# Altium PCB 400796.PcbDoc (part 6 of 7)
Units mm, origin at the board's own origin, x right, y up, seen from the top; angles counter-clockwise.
Board outline 53 x 53 mm, 6 copper layers (Top Layer, Mid Layer 1, Mid Layer 2, Mid Layer 3, Mid Layer 4, Bottom Layer), stack 1.494 mm thick; 319 components, 236 nets, 1249 pads, 2569 vias.
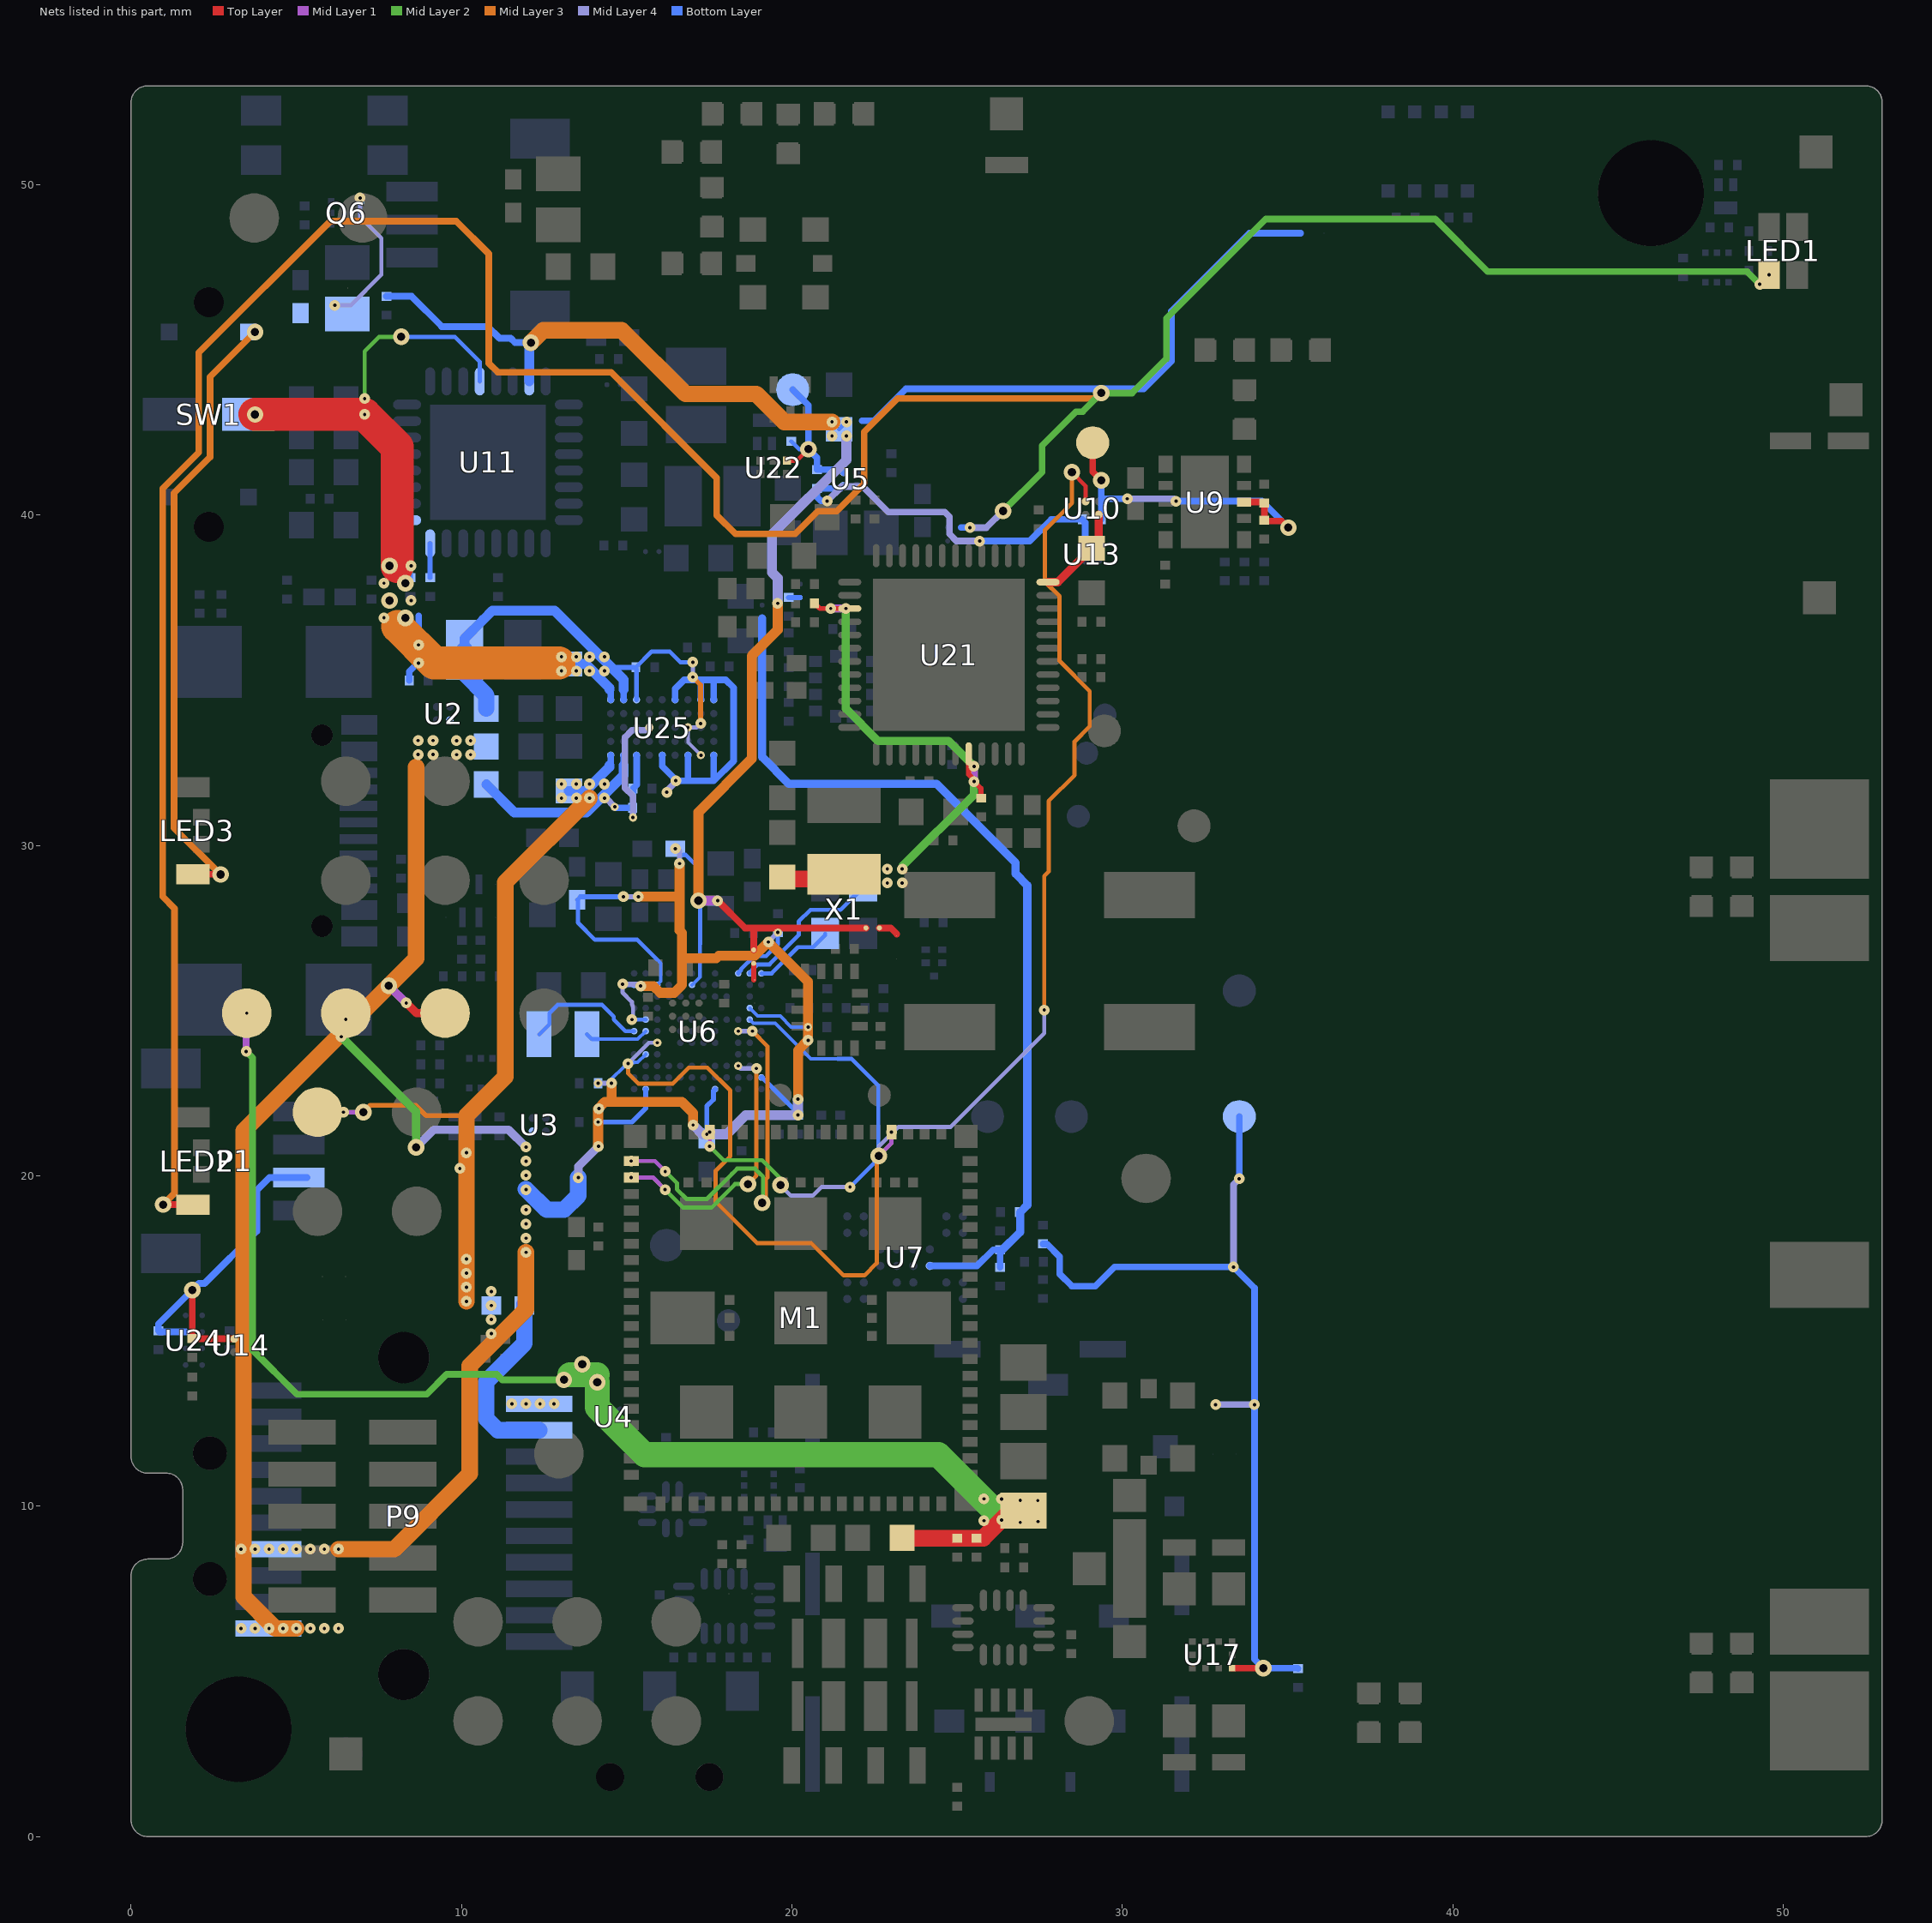
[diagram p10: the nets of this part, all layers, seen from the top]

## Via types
v1: diameter 0.325, hole 0.1, Mid Layer 4 to Bottom Layer, tented both sides, 675 vias
v2: diameter 0.325, hole 0.1, Top Layer to Mid Layer 1, tented both sides, 569 vias
v3: diameter 0.325, hole 0.1, Mid Layer 3 to Mid Layer 4, tented both sides, 384 vias
v4: diameter 0.5, hole 0.25, Mid Layer 1 to Mid Layer 4, tented both sides, 312 vias
v5: diameter 0.325, hole 0.1, Mid Layer 1 to Mid Layer 2, tented both sides, 265 vias
v6: diameter 0.5, hole 0.25, Top Layer to Bottom Layer, tented both sides, 175 vias
v7: diameter 0.25, hole 0.1, Mid Layer 4 to Bottom Layer, tented both sides, 105 vias
v8: diameter 0.325, hole 0.1, Top Layer to Mid Layer 1, tented top, 67 vias
v9: diameter 0.25, hole 0.1, Top Layer to Mid Layer 1, tented both sides, 17 vias

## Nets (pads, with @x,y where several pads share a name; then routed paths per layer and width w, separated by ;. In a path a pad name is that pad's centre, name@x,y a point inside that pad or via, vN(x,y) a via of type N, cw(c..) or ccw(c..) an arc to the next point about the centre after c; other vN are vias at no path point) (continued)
VCOM0.TXD: M1.56 U6.E2 | length 13.7
  Mid Layer 1 w0.125: v5(17.513,20.895) v2(17.513,21.325)
  Mid Layer 2 w0.125: v5(17.513,20.895) 17.932,20.477 19.099,20.477 19.653,19.923 v4(19.653,19.72)
  Mid Layer 4 w0.125: v4(19.653,19.72) 19.97,19.403 20.631,19.403 20.891,19.663 v1(21.758,19.663)
  Bottom Layer w0.105: U6.E2@18.725,24.73 18.832,24.623 19.497,24.623 20.573,23.546 21.387,23.546
  Bottom Layer w0.125: 21.387,23.546 21.802,23.546 22.613,22.735 22.613,20.518 v1(21.758,19.663)
VCOM1.RXD: M1.62 U6.J3 | length 8.4
  Mid Layer 1 w0.125: v2(15.138,19.95) 15.798,19.95 v5(16.163,19.585)
  Mid Layer 2 w0.125: v5(16.163,19.585) 16.711,19.038 17.562,19.038 18.277,19.753 v4(18.672,19.753)
  Mid Layer 3 w0.125: v4(18.672,19.753) 18.927,20.007 v3(18.927,23.254)
  Mid Layer 4 w0.15: v7(18.375,23.33) 18.451,23.254 v3(18.927,23.254)
VCOM1.TXD: M1.61 U6.F3 | length 11.7
  Mid Layer 1 w0.125: v2(15.138,20.45) 15.853,20.45 v5(16.167,20.136)
  Mid Layer 2 w0.125: v5(16.167,20.136) 16.519,19.783 16.519,19.594 16.812,19.301 17.424,19.301 18.185,20.062 18.341,20.218 18.882,20.218 19.039,20.062 19.123,19.978 19.123,19.212 v4(19.096,19.185)
  Mid Layer 3 w0.127: v3(18.806,24.38) 19.259,23.927 19.259,19.95 19.214,19.906 19.214,19.303 v4(19.096,19.185)
  Mid Layer 4 w0.15: v7(18.375,24.38) v3(18.806,24.38)
VDD_ACC: R26.1 ST7.2 | length 0.4
  Bottom Layer w0.152: R26.1@19.9,37.51 ST7.2@20.253,37.51
VDD_BMI270: SB4.1 ST1.2 | length 0.6
  Top Layer w0.203: ST1.2@22.648,27.506 22.99,27.506 23.173,27.323
VDD_BMM350: SB10.1 ST4.2 | length 0.5
  Top Layer w0.152: 18.841,25.928 ST4.2@18.841,26.434
VDD_BUCK: C60.2 C65.2 C70.2 L6.2 U21.15 U21.32 | length 17
  Top Layer w0.152: C70.2@20.68,37.338 20.68,37.323 20.739,37.264 20.754,37.264 20.843,37.175 v2(21.175,37.175) U21.15@21.75,37.175 ; U21.32@25.35,32.775 25.35,32.153 25.513,31.99 v2(25.513,31.94) 25.725,31.728 C60.2@25.725,31.435
  Top Layer w0.508: C65.2@19.83,28.993 L6.2@20.942,28.993 ; L6.2@21.075,29.127 L6.2@20.942,28.993 ; L6.2@21.442,28.993 L6.2@20.942,28.993
  Mid Layer 1 w0.25: v2(21.175,37.175) v5(21.632,37.175) ; v2(25.513,31.94) v5(25.513,32.397)
  Mid Layer 2 w0.25: v5(21.632,37.175) 21.632,34.146 22.613,33.165 24.745,33.165 v5(25.513,32.397) 25.513,31.54 23.338,29.365 v5(23.338,29.292)
  other v2: 22.888,28.867 22.888,29.292
  other v5: 23.338,28.867
VDD_ENV: SB5.1 ST5.2 | length 16.5
  Bottom Layer w0.2: ST5.2@22.128,42.859 22.484,42.859 23.45,43.825 30.65,43.825 31.487,44.662 31.487,46.176 33.849,48.538 SB5.1@35.4,48.538
VDD_EXP_BRD: C76.2 P1.2 R5.1 U14.A1 U24.B2 | length 10.8
  Top Layer w0.203: v6(1.854,16.544) R5.1@1.854,15.072 3.109,15.072 U14.A1@3.11,15.073
  Bottom Layer w0.203: U24.B2@1.65,15.275 0.86,15.275 C76.2@0.825,15.31 0.825,15.516 v6@1.815,16.506 ; v6(1.854,16.544) 2.051,16.742 2.223,16.742 3.802,18.321 3.802,19.562 4.19,19.95 P1.2@5.325,19.95
VDD_LED: LED1.4 LED2.4 ST2.2 | length 96.1
  Top Layer w0.2: v6(0.968,19.129) LED2.4@1.873,19.129
  Mid Layer 1 w0.15: v5(49.292,46.992) v2(49.575,47.275)
  Mid Layer 2 w0.2: v4(26.393,40.129) 27.571,41.307 27.571,42.108 28.595,43.132 28.797,43.132 v4(29.365,43.7) 30.301,43.7 31.339,44.738 31.339,45.958 34.349,48.968 39.465,48.968 41.06,47.373 48.911,47.373 v5(49.292,46.992)
  Mid Layer 3 w0.2: v6(0.968,19.129) 1.313,19.475 1.313,28.094 0.954,28.453 0.954,40.812 2.046,41.904 2.046,44.922 6.024,48.9 9.841,48.9 10.825,47.916 10.825,44.6 11.1,44.325 14.528,44.325 17.725,41.128 17.725,40 18.292,39.433 20.094,39.433 20.786,40.125 21.352,40.125 22.185,40.958 22.185,42.519 23.203,43.537 29.203,43.537 v4(29.365,43.7)
  Mid Layer 4 w0.2: v1(25.39,39.625) 25.889,39.625 v4(26.393,40.129)
  Bottom Layer w0.2: ST2.2@25.121,39.628 25.387,39.628 v1(25.39,39.625)
VDD_MEM: C37.2 R43.2 R50.2 ST9.2 U7.C3 | length 28.3
  Bottom Layer w0.2: U7.C3@24.175,17.275 25.6,17.275 26.09,17.765 C37.2@26.3,17.765 R50.2@26.3,17.235
  Bottom Layer w0.25: ST9.2@19.1,36.875 ST9.2@19.1,36.872 19.1,32.675 19.907,31.868 24.381,31.868 26.77,29.479 26.77,29.145 27.125,28.79 27.125,19.115 26.91,18.9 26.91,18.297 C37.2@26.326,17.713
VDD_nRF53: C12.1 C13.1 C15.1 C16.1 C19.1 C20.1 C21.1 C22.2 P9.4 TP2.1 U3.A1 U6.A3 U6.B7 U6.B10 U6.B12 U6.D2 U6.E11 U6.H11 U6.K1 U6.L5 U6.L11 | length 75
  Top Layer w0.15: v2(6.498,24.734) 6.5,24.735 TP2.1@6.5,24.927
  Mid Layer 1 w0.15: v5(6.358,24.212) 6.498,24.352 v2(6.498,24.734)
  Mid Layer 2 w0.254: v5(6.358,24.212) 8.624,21.945 v4(8.624,20.863)
  Mid Layer 3 w0.3: v3@14.135,20.905 14.135,22.035 14.34,22.24 16.672,22.24 17.008,21.904 v3(17.008,21.537) ; 14.54,22.25 v3(14.54,22.805) ; v3(15.35,28.45) 16.6,28.45 ; v3(15.42,25.746) 15.81,25.746 16.014,25.542 16.436,25.542 16.676,25.783 16.676,26.583 ; v3(16.6,29.455) 16.6,28.45 ; v3(20.184,22.321) 20.184,23.799 v3(20.49,24.105) 20.49,25.879 v3(19.287,27.082) 18.874,26.67 17.792,26.67 17.705,26.583 16.676,26.583 ; 16.6,28.45 16.6,27.433 16.676,27.356 16.676,26.583
  Mid Layer 3 w0.5: v3(6.275,8.7) 7.969,8.7 10.25,10.981 10.25,14.25 11.95,15.95 v3(11.95,17.685)
  Mid Layer 4 w0.125: v1(14.875,25.805) 14.875,25.55 15.156,25.268 15.156,25.187 15.17,25.174 15.17,25.166 15.178,25.158 15.178,25.126 15.191,25.113 15.191,24.763 v1(15.159,24.73)
  Mid Layer 4 w0.15: v7(14.135,21.63) v3@14.135,22.03 ; v7(14.135,22.805) v3@14.535,22.805 ; v1(14.875,25.805) 15.361,25.805 v3(15.42,25.746) ; v1(14.9,28.45) v3(15.35,28.45) ; v3(16.6,29.455) v1@16.6,29.855 ; v3@19.292,27.087 v7(19.575,27.37) ; v3(20.49,24.105) v7(20.49,24.505)
  Mid Layer 4 w0.254: v4(8.624,20.863) 9.157,21.395 11.43,21.395 v1(11.95,20.875) ; v1(13.534,19.949) 13.534,20.285 v3(14.145,20.895)
  Mid Layer 4 w0.3: v3(17.008,21.537) 17.017,21.537 17.298,21.257 v1(17.425,21.257)
  Mid Layer 4 w0.305: v1(17.425,21.257) 18.016,21.257 18.599,21.84 v1(20.184,21.84) v3(20.184,22.321)
  Bottom Layer w0.105: C20.1@14.148,22.805 14.41,22.805 15.037,23.433 15.22,23.433 15.225,23.437 15.332,23.437 U6.H11@15.575,23.68 ; 15.92,26.55 16.032,26.438 16.032,25.887 U6.B10@15.925,25.78 ; U6.B7@16.975,25.78 17.217,26.023 17.217,27.05 ; U6.D2@18.725,25.08 18.967,24.838 19.65,24.838 19.98,24.507 C12.1@20.471,24.507
  Bottom Layer w0.125: C22.2@13.5,28.355 C22.2@13.595,28.45 ; C22.2@13.525,28.355 13.525,27.665 14.039,27.151 15.319,27.151 15.92,26.55 ; v7(14.135,22.805) C20.1@14.148,22.805 ; v1(15.159,24.73) U6.E11@15.575,24.73 ; v1(16.475,29.905) 16.662,29.718 16.787,29.718 17.225,29.28 17.225,27.025 ; U6.A3@18.375,26.13 18.375,26.142 18.452,26.22 18.452,26.246 18.858,26.653 19.218,26.653 19.575,27.009 C21.1@19.575,27.27
  Bottom Layer w0.15: C22.2@13.595,28.45 v1(14.9,28.45) ; v7(14.135,21.63) 15.157,21.63 15.575,22.047 U6.L11@15.575,22.63 ; v1(14.875,25.805) 14.9,25.78 U6.B12@15.225,25.78 ; v1(17.425,21.257) 17.425,22.114 17.623,22.312 17.623,22.579 U6.L5@17.675,22.63 ; U6.K1@19.075,22.98 19.078,22.976 19.103,22.976 C13.1@20.184,21.896
  Bottom Layer w0.5: v1@11.95,19.6 12.575,18.975 13.104,18.975 13.534,19.405 v1(13.534,19.949)
  other v1: 3.325,8.7 3.75,8.7 4.175,8.7 4.6,8.7 11.95,19.585 11.95,20.015 11.95,20.445
  other v3: 5,8.7 5.425,8.7 5.85,8.7 11.95,18.115 11.95,18.545 11.95,18.975 14.16,22.035
VDD_nRF91: C1.1 C2.1 C3.1 FB1.1 P9.11 TP3.1 U4.A1 | length 39.5
  Top Layer w0.508: FB1.1@23.332,9.03 C2.1@25.587,9.03 ; C2.1@25.583,9.033 25.791,9.033 26.623,9.865 C3.1@27.006,9.865
  Mid Layer 1 w0.203: v5(3.481,23.767) 3.481,24.909 v2(3.5,24.927)
  Mid Layer 2 w0.203: v5(3.481,23.767) 3.675,23.573 3.675,14.731 5.016,13.391 8.95,13.391 9.551,13.991 11.069,13.991 11.234,13.826 v4(13.099,13.826)
  Mid Layer 2 w0.762: v4@13.283,13.979 v4@14.109,13.979 ; v4(14.109,13.75) 14.109,12.993 15.543,11.558 24.436,11.558 25.792,10.203 26.129,9.865
  other v1: 11.525,13.1 11.95,13.1 12.375,13.1 12.8,13.1
  other v2: 26.911,9.511 27.446,9.534 26.911,10.174 27.442,10.171
  other v4: 13.655,14.301
  other v5: 25.813,9.56 26.348,9.583 25.813,10.223 26.344,10.22
VDD_nRF91_RES: P9.12 R24.1 U4.A2 | length 5.7
  Bottom Layer w0.5: R24.1@11.9,16.113 11.9,14.925 10.75,13.775 10.75,12.65 11.1,12.3 P9.12@12.35,12.3
VDD_RF_FE_3V3: C32.2 C33.2 R56.1 TP8.1 U9.3 U13.A1 | length 10.9
  Top Layer w0.2: TP8.1@29.105,42.194 29.105,41.314 v6(29.36,41.059) ; U9.3@33.688,40.4 34.133,40.4 ; C32.2@34.3,40.233 34.3,39.825 34.825,39.825 v6(35.025,39.625)
  Mid Layer 4 w0.2: v1(30.15,40.5) 31.55,40.5 v1(31.625,40.425)
  Bottom Layer w0.2: U13.A1@29.275,39.028 R56.1@29.275,39.793 ; R56.1@29.36,39.878 29.36,40.5 ; v6(29.36,41.059) 29.36,40.5 ; v1(30.15,40.5) 29.36,40.5 ; v1(31.625,40.425) 34.225,40.425 v6(35.025,39.625)
VDD_RF_FE_3V3_SP: R25.2 R56.2 ST3.2 U5.A2 U13.A2 | length 12.1
  Mid Layer 4 w0.2: v1(21.069,40.431) 21.506,40.868 22.146,40.868 22.918,40.096 24.624,40.096 24.766,39.954 24.766,39.433 24.979,39.219 v1(25.683,39.219)
  Bottom Layer w0.2: v1(21.069,40.431) 20.879,40.431 20.761,40.549 R25.2@20.761,40.814 21.476,40.814 U5.A2@21.561,40.899 ; ST3.2@25.121,39.219 v1(25.683,39.219) 27.194,39.219 27.853,39.878 R56.2@28.79,39.878 ; R56.2@28.783,39.878 R56.2@28.786,39.875 ; R56.2@28.79,39.863 28.875,39.778 U13.A2@28.875,39.028
VDD_RF_FE_SR: R25.1 R62.1 TP11.1 U5.A1 U22.4 | length 5
  Top Layer w0.125: U22.4@19.85,41.65 20.15,41.65 v6(20.5,42)
  Bottom Layer w0.125: R62.1@19.975,42.24 20.215,42 v6(20.5,42)
  Bottom Layer w0.2: TP11.1@20.025,43.8 20.5,43.325 v6(20.5,42) 20.761,41.739 R25.1@20.761,41.384 21.476,41.384 U5.A1@21.561,41.299
VDD_SENS: C90.2 R30.2 ST1.1 ST4.1 ST5.1 U11.31 | length 39.5
  Top Layer w0.203: v2(17.753,28.332) 18.579,27.506 18.846,27.506 ; ST4.1@18.841,26.84 18.841,27.501 18.846,27.506 ; ST1.1@22.242,27.506 18.846,27.506
  Mid Layer 1 w0.305: v4(17.172,28.332) v2(17.753,28.332)
  Mid Layer 3 w0.305: v4(17.172,28.332) 17.172,31.016 18.787,32.631 18.787,35.744 19.569,36.526 v3(19.569,37.332)
  Mid Layer 3 w0.5: v6(12.1,45.225) 12.475,45.6 14.85,45.6 16.779,43.671 18.923,43.671 19.769,42.825 v3(21.213,42.825)
  Mid Layer 4 w0.125: v1(21.213,42.4) v3(21.213,42.825)
  Mid Layer 4 w0.305: v3(19.569,37.332) 19.569,38.098 19.398,38.269 19.398,39.421 21.65,41.674 v1(21.65,42.4)
  Bottom Layer w0.125: C90.2@21.425,42.6 21.684,42.859 ST5.1@21.722,42.859
  Bottom Layer w0.203: R30.2@7.726,46.628 8.485,46.628 9.401,45.712 10.795,45.712 11.149,45.358 11.487,45.358 11.62,45.225 v6@12.05,45.225
  Bottom Layer w0.3: U11.31@12.05,44.05 12.05,45.225 v6(12.1,45.225)
  other v3: 21.65,42.825
VDDIO_CTRL: M1.45 U6.G10 U10.B2 | length 45
  Top Layer w0.125: v6(28.475,41.3) 28.888,40.887 U10.B2@28.888,40.415
  Mid Layer 1 w0.125: v4(22.629,20.604) 23.013,20.988 v2(23.013,21.325)
  Mid Layer 3 w0.125: v3(15.039,23.4) 15.039,23.104 15.347,22.795 16.394,22.795 16.875,23.276 17.441,23.276 18.134,22.583 18.134,20.598 17.693,20.157 17.693,19.222 18.953,17.962 20.586,17.962 21.562,16.987 22.196,16.987 22.567,17.357 22.567,20.542 v4(22.629,20.604) ; v3(27.637,25.023) 27.637,29.079 27.771,29.213 27.771,31.349 28.555,32.134 28.555,33.147 29.014,33.606 29.014,34.671 28.097,35.588 28.097,37.548 27.657,37.988 27.657,39.555 28.475,40.373 v6(28.475,41.3)
  Mid Layer 4 w0.125: v3(15.039,23.4) 15.669,24.03 v7(15.925,24.03) ; v4(22.629,20.604) 22.629,20.887 23.225,21.483 24.803,21.483 27.637,24.317 v3(27.637,25.023)
VDDIO_nRF70: C30.2 U10.A1 U21.48 | length 2.8
  Top Layer w0.254: U21.48@27.75,37.975 28.05,37.975 C30.2@29.075,39 C30.2@29.263,39.188 ; C30.2@29.288,39.188 U10.A1@29.288,40.015
VIO: C38.2 R29.2 SB1.1 TP21.1 U17.4 | length 27.1
  Top Layer w0.2: U17.4@33.318,5.1 v6(34.268,5.1)
  Mid Layer 4 w0.2: v1(32.825,13.075) v1(34,13.075) ; v1@33.364,17.266 33.364,19.738 v1(33.537,19.911)
  Bottom Layer w0.2: R29.2@27.6,17.94 27.71,17.94 28.102,17.549 28.102,17.031 28.476,16.656 29.183,16.656 29.768,17.241 v1(33.364,17.241) 34,16.605 v1(34,13.075) 34,5.368 v6(34.268,5.1) 35.305,5.1 C38.2@35.32,5.085 ; v1(33.537,19.911) 33.54,19.914 TP21.1@33.54,21.795
VOUT_BUCK0: C78.2 C82.1 L9.2 U25.B1 U25.C3 U25.G5 U25.H5 | length 16.1
  Mid Layer 3 w0.15: v3(17,35.1) 17.237,34.863 v3(17.237,33.695)
  Mid Layer 4 w0.105: v7(16.855,33.575) 16.855,33.125 v7(17.245,32.735)
  Mid Layer 4 w0.125: v7(16.855,33.575) 17.116,33.575 v3(17.237,33.695) ; v3(17,35.1) v1(17,35.55)
  Bottom Layer w0.125: C82.1@15.225,35.39 15.271,35.39 15.756,35.875 16.3,35.875 16.625,35.55 v1(17,35.55)
  Bottom Layer w0.15: 14.56,35.39 C82.1@15.225,35.39 ; U25.G5@15.295,34.415 C82.1@15.295,35.331
  Bottom Layer w0.2: U25.H5@14.905,34.415 14.905,34.72
  Bottom Layer w0.3: L9.2@10.09,35.925 10.09,36.27 10.655,36.835 10.93,37.11 12.815,37.11 14.905,35.02 14.905,34.72
  Bottom Layer w0.5: L9.2@10.09,35.925 10.09,35.21 10.75,34.55 C78.2@10.75,34.15
VOUT_BUCK3: C81.2 L10.2 P9.1 TP14.1 U2.A2 U25.H1 | length 36.9
  Top Layer w0.254: v2(8.328,25.233) 8.332,25.233 8.638,24.927 TP14.1@9.5,24.927
  Mid Layer 1 w0.254: v4(7.799,25.756) 7.805,25.756 v2(8.328,25.233)
  Mid Layer 3 w0.5: v3(5,6.3) 4.362,6.3 3.4,7.262 3.4,21.356 v4(7.799,25.756) 8.625,26.581 8.625,32.375
  Bottom Layer w0.2: 14.905,32.43 U25.H1@14.905,32.735
  Bottom Layer w0.3: L10.2@10.75,31.85 11.6,31 13.775,31 14.905,32.13 14.905,32.43
  other v1: 3.325,6.3 3.75,6.3 4.175,6.3 4.6,6.3 9.85,32.75 10.275,32.75 9.85,33.175 10.275,33.175
  other v3: 5.425,6.3 5.85,6.3 6.275,6.3 8.688,32.755 9.138,32.755 8.688,33.18 9.138,33.18
VSET1: R7.1 U11.17 | length 1.9
  Bottom Layer w0.15: U11.17@8.1,39.781 8.169,39.85 U11.17@8.35,39.85 ; R7.1@8.45,38.11 U11.17@8.45,39.781
VSET2: R8.1 U11.16 | length 1
  Bottom Layer w0.15: R8.1@9.05,38.11 U11.16@9.05,39.15
VSYS: C98.2 FB5.2 LED3.4 Q6.4 SW1.6 | length 23.2
  Top Layer w0.2: LED3.4@1.873,29.129 2.699,29.129 v6(2.705,29.123)
  Mid Layer 3 w0.2: v6(2.705,29.123) 1.299,30.53 1.299,40.669 2.388,41.758 2.388,44.188 v6(3.75,45.55)
  Mid Layer 4 w0.125: v1(6.165,46.357) 6.647,46.357 7.573,47.283 7.573,48.39 6.929,49.034 v1(6.929,49.605)
VSYS_SW: C77.2 C80.2 C83.1 C84.1 R3.2 R24.2 SW1.5 TP17.1 U11.28 U25.A1 U25.A5 U25.B5 U25.C1 U25.D5 U25.E1 U25.F3 U25.G1 U25.J1 U25.J5 | length 65.6
  Top Layer w0.152: TP17.1@5.642,21.927 v2(6.428,21.927)
  Top Layer w1: v6(3.75,43.05) v2(7.067,43.05) 8.05,42.067 8.05,38.45
  Mid Layer 1 w0.125: v2(7.067,43.05) v5(7.067,43.533)
  Mid Layer 1 w0.152: v2(6.428,21.927) v4(7.026,21.927)
  Mid Layer 2 w0.125: v5(7.067,43.533) 7.067,44.962 7.507,45.402 v6(8.175,45.402)
  Mid Layer 3 w0.152: v4@6.976,21.927 v4@7.001,21.953 ; v4(7.026,21.927) 7.234,22.135 8.615,22.135 8.925,21.825 10.15,21.825
  Mid Layer 3 w0.3: 10.148,19.9 10.15,19.898
  Mid Layer 3 w0.5: v3(10.15,16.2) v3(10.15,16.63) v3(10.15,17.055) v3(10.15,17.48) 10.15,19.898 10.15,21.825 11.325,23 11.325,28.887 v3(13.875,31.437)
  Mid Layer 3 w1: 8.063,36.637 9.175,35.525 12.95,35.525
  Mid Layer 4 w0.2: v3(8.7,35.525) v1(8.7,36.075) ; v3(14.325,31.438) 14.369,31.438 v7(14.637,31.17) ; v7(15.19,30.851) 15.19,31.501 14.945,31.746 14.945,33.275 15.16,33.49 15.6,33.49 v7(15.685,33.575) ; v3@16.214,31.663 v1@16.513,31.962
  Mid Layer 4 w0.3: v1(9.95,20.225) 10.15,20.425 v3(10.15,20.7)
  Bottom Layer w0.125: v6(8.175,45.402) 9.798,45.402 10.55,44.65 U11.28@10.55,44.05
  Bottom Layer w0.2: R3.2@8.415,35 8.415,35.265 8.7,35.55 v1(8.7,36.075) 8.7,36.95 ; 14.515,32.43 U25.J1@14.515,32.735 ; U25.J5@14.515,34.415 14.515,34.72 ; v7(14.637,31.17) 14.662,31.145 C83.1@15.177,31.145 C83.1@15.19,31.132 ; v7(15.19,30.851) C83.1@15.19,31.132 ; U25.G1@15.295,32.735 15.299,32.731 15.299,32.717 15.305,32.711 15.305,31.84 C84.1@15.19,31.725 15.19,31.145 C83.1@15.19,31.132 ; U25.E1@16.075,32.735 16.075,32.4 16.513,31.962 16.855,31.962 ; U25.D5@16.465,34.415 16.465,34.743 16.737,35.015 17.245,35.015 ; 16.855,31.964 U25.C1@16.855,32.735 ; 16.857,31.962 17.635,31.962 ; U25.B5@17.245,34.415 17.245,35.015 ; U25.A1@17.635,32.735 17.635,32.135 17.635,31.963 ; U25.A5@17.635,34.415 17.635,35.015 ; 17.245,35.015 17.635,35.015 ; 17.636,31.962 18.237,32.563 18.237,32.815 18.237,34.776 17.998,35.015 17.635,35.015
  Bottom Layer w0.3: C80.2@13.25,31.65 13.75,31.65 14.48,32.38 14.48,32.43 ; C77.2@13.25,35.5 13.75,35.5 14.48,34.77 14.48,34.72
  other v1: 10.9,15.225 10.9,15.65 10.9,16.075 10.9,16.5 13.025,31.438 13.475,31.437 13.025,31.863 13.475,31.863 16.488,31.962 13.025,35.288 13.475,35.288 13.025,35.713 13.475,35.713
  other v2: 7.652,36.893 8.473,37.418 7.652,37.943 8.473,38.468
  other v3: 16.214,31.612 13.875,31.863 14.325,31.863 13.875,35.288 14.325,35.288 13.875,35.713 14.325,35.713
  other v4: 8.302,36.893 7.823,37.418 8.302,37.943 7.823,38.468
XC1: U6.A1 X1.1 | length 2.5
  Bottom Layer w0.125: U6.A1@19.075,26.13 19.389,26.13 20.182,26.923 20.642,26.923 21.005,27.285 X1.1@21.005,27.335
XC2: U6.A2 X1.3 | length 4.8
  Bottom Layer w0.125: U6.A2@18.725,26.13 18.725,26.142 18.802,26.22 18.802,26.243 18.962,26.403 19.321,26.403 20.205,27.286 20.205,27.701 20.559,28.055 21.475,28.055 22.155,28.735 X1.3@22.155,28.785
XL1: U6.F11 X2.1 | length 1.9
  Bottom Layer w0.105: X2.1@14.148,24.138 15.332,24.138 U6.F11@15.575,24.38
  Bottom Layer w0.125: X2.1@13.795,24.29 13.947,24.138 X2.1@14.148,24.138
XL2: U6.F12 X2.2 | length 3.8
  Bottom Layer w0.125: X2.2@12.35,24.28 12.662,24.593 12.662,24.924 12.918,25.18 14.25,25.18 14.608,24.822 14.608,24.731 14.959,24.38 U6.F12@15.225,24.38
pads on no net: A1.0 A2.1 A2.2 A2.3 A3.0 D3. D3.4 Fid1.0 Fid2.0 H1. H2. J3.0 J4.C6 J6.0 J6.A8 J6.B8 M1.21 M1.22 M1.23 M1.26 M1.31 M1.32 M1.33 M1.37 M1.81 M1.82 M1.83 M1.84 M1.85 M1.86 M1.87 M1.88 M1.89 M1.90 M1.91 M1.92 M1.93 M1.94 M1.95 M1.96 M1.97 M1.98 M1.100 M1.102 M1.103 M1.104 P1.0 P8.0 P8.6 P8.7 P8.8 P9. P9.13 SW1.0 SW2.0 U1.7 U1.8 U1.9 U1.10 U6.C7 U6.C9 U6.D11 U6.H2 U6.H12 U6.J4 U6.J5 U6.J6 U6.K8 U6.K10 U7.A1 U7.A5 U7.A6 U7.B1 U7.B2 U7.B5 U7.B6 U7.D1 U7.D2 U7.D6 U7.E1 U7.E2 U7.E5 U7.E6 U7.G1 U7.G2 U7.G5 U7.G6 U7.H1 U7.H2 U7.H5 U7.H6 U8.4 U9. U12.9 U15.0 U15.2 U15.4 U15.5 U16.10 U18.9 U18.10 U18.11 U20.6 U20.8 U21.6 U21.21 U21.22 U21.23 U21.24 U25.A2 U25.A4 U25.B4 U25.C5 U25.D1 U25.D4 U25.E4

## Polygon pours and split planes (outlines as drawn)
GND on Mid Layer 3 "Mid_Layer_3-GND" (solid, remove dead copper, pour order 114): 53,0 0,0 0,53 53,53
VSYS_SW on Mid Layer 3 "Mid_Layer_2-Vin" (solid, pour order 14): 15.75,32.9 16.925,31.725 16.925,31.226 13.587,31.226 13.587,36.025 15.75,36.025
GND on Bottom Layer "Bottom_Layer-GND" (solid, remove dead copper, pour order 116): 53,0 0,0 0,53 53,53
Shield on Bottom Layer "SHIELD_L06_P115" (solid, pour order 115): -0.006,37.21 3.371,37.21 3.371,36.65 7.28,36.65 7.28,34.141 5.396,34.141 5.396,26.696 7.28,26.696 7.28,24.25 0,24.25 0,25.216
GND on Mid Layer 1 "Mid_Layer_1-GND" (solid, remove dead copper, pour order 12): 52.454,0.014 -0.546,0.014 -0.546,53.014 52.454,53.014
GND on Top Layer "Top_Layer-GND" (solid, remove dead copper, pour order 10): 53,0 0,0 0,53 53,53
GND on Mid Layer 2 "Mid_Layer_2-GND" (solid, remove dead copper, pour order 110): 53,0 0,0 0,53 53,53
GND on Mid Layer 4 "Mid_Layer_4-GND" (solid, remove dead copper, pour order 111): 53,0 0,0 0,53 53,53

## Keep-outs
Top Layer:
  rectangle: -0.173,25.765 1.139,27.27
Mid Layer 1:
  region: 30.645,5.387 30.645,5.521 cw(c32.096,5.521) 31.07,6.547 ccw(c30.103,7.514) 31.47,7.514 31.47,7.647 30.069,7.647 30.069,5.387
  region: 33.334,4.123 32.556,5.075 32.069,5.075 31.291,4.124
  region: 33.333,6.876 32.556,5.925 32.067,5.925 31.289,6.875
  region: 38.45,3.525 31.59,3.525 31.59,0.975 38.45,0.975
  region: 38.45,10.025 32.095,10.025 32.095,7.475 38.45,7.475
  region: 35.545,3.603 35.545,10.025 38.203,10.025 38.203,3.603
  region: 37.565,5.012 36.566,5.012 36.566,8.512 31.81,8.512 31.81,8.987 37.041,8.987 37.041,5.487 39.541,5.487 39.541,4.012 37.565,4.012
  region: 35.34,2 44.596,2 44.596,2.487 35.34,2.487
  lines w0.29: 17.582,47.623 18.608,47.623 ; 18.075,30.9 17.502,30.9 cw(c17.502,32.048) 16.354,32.048 16.354,40.077 cw(c17.526,40.077) 17.526,41.25 18.757,41.25 ; 19.45,41.682 19.45,43.15 ; 19.95,43.95 19.95,44.376 cw(c21.024,44.376) 20.265,45.136 20.275,45.146 cw(c20.8,44.622) 20.8,45.364 ccw(c20.8,45.959) 21.22,45.538 21.254,45.572 ccw(c20.421,46.406) 21.6,46.406 21.6,47.201 ccw(c21.173,47.201) 21.475,47.503 ccw(c21.183,47.211) 21.183,47.623 20.928,47.623 ; 20.145,41.25 22.85,41.25 cw(c22.85,40.35) 23.75,40.35 23.75,39.35 ; 20.475,43.05 23.324,43.05 cw(c23.324,41.824) 24.55,41.824 24.55,39.35
  lines w0.638: 24.513,22.086 24.513,22 cw(c25.436,22) 24.783,22.652 cw(c25.367,22.068) 25.367,22.894 32.036,22.894 ccw(c32.036,25.169) 33.645,23.56 ccw(c32.075,25.131) 34.296,25.131 34.296,31.648 ccw(c31.756,31.648) 33.552,33.444 32.04,34.956 cw(c33.836,36.752) 31.296,36.752 31.296,37.78 ; 26.061,17.949 27.386,17.949 cw(c27.386,15.409) 29.182,17.205 30.056,16.331 cw(c28.26,14.535) 30.8,14.535 30.8,13.56 ; 30.219,10.295 30.564,10.64 ccw(c29.994,11.21) 30.8,11.21 ; 31.3,37.78 31.3,36.752 ccw(c33.84,36.752) 32.044,34.956 33.556,33.444 cw(c31.76,31.648) 34.3,31.648 ; 31.313,38.625 31.313,39.256 ; 33.688,41.543 33.688,42.577 ; 33.7,43.81 33.7,44.99 ; 33.71,45 34.79,45
  lines w0.69: 19.95,52.15 24.85,52.15
Mid Layer 2:
  lines w1.14: 19.95,52.15 24.85,52.15
Mid Layer 4:
  lines w0.29: 18.075,30.9 19.025,30.9 23.65,30.9 cw(c23.65,30) 24.55,30 24.55,26.902 ; 22.231,25.08 23.704,25.08 ccw(c23.704,25.676) 24.299,25.676 24.299,26.051
Bottom Layer:
  rectangle: 35.046,23.695 38.362,29.305
  rectangle: -0.237,48.713 3.22,50.218
Keep-Out Layer:
  circle w0.152: c32.1,53 r0.173
  circle w0.152: c31.3,53 r0.173
  circle w0.152: c30.5,53 r0.173
  circle w0.152: c29.7,53 r0.173
  circle w0.152: c28.9,53 r0.173
  circle w0.152: c28.9,0 r0.173
  circle w0.152: c29.7,0 r0.173
  circle w0.152: c30.5,0 r0.173
  circle w0.152: c31.3,0 r0.173
  circle w0.152: c32.1,0 r0.173
  circle w0.152: c53,5.6 r0.173
  circle w0.152: c53,4.8 r0.173
  circle w0.152: c53,4 r0.173
  circle w0.152: c53,3.2 r0.173
  circle w0.152: c53,2.4 r0.173
  circle w0.152: c53,48.2 r0.173
  circle w0.152: c53,47.4 r0.173
  circle w0.152: c53,5.6 r0.173
  circle w0.152: c53,4.8 r0.173
  circle w0.152: c53,4 r0.173
  circle w0.152: c53,3.2 r0.173
  circle w0.152: c53,2.4 r0.173
  circle w0.152: c0,5.6 r0.173
  circle w0.152: c0,4.8 r0.173
  circle w0.152: c0,4 r0.173
  circle w0.152: c0,3.2 r0.173
  circle w0.152: c0,2.4 r0.173
  circle w0.152: c0,50.6 r0.173
  circle w0.152: c0,49.8 r0.173
  circle w0.152: c0,49 r0.173
  circle w0.152: c0,48.2 r0.173
  circle w0.152: c0,47.4 r0.173
  circle w0.152: c53,50.6 r0.173
  circle w0.152: c53,49.8 r0.173
  circle w0.152: c53,49 r0.173
  circle w0.152: c53,48.2 r0.173
  circle w0.152: c53,47.4 r0.173

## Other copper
Top Layer:
  rectangle net 1V8_SW: 13.192,18.116 13.745,18.879
  rectangle net NetA3_1: 22.2,51.9 26.5,52.4
  rectangle net NetA1_1: 37.102,2.4 39.102,3.502
  region net VSYS_SW: 7.487,38.743 7.487,36.693 8.637,36.693 8.637,38.743
  region net NetJ1_1: 25.242,18.1 25.661,18.1 ccw(c25.661,18.356) 25.842,18.175 25.842,17.725 ccw(c25.661,17.544) 25.661,17.8 25.242,17.8
  region net GPS_RF1: 24.367,21.175 24.367,21.594 ccw(c24.111,21.594) 24.292,21.775 24.742,21.775 ccw(c24.923,21.594) 24.667,21.594 24.667,21.175
  region net NetJ1_3: 31.05,11.53 cw(c30.884,11.364) 31.119,11.364 31.119,11.21 30.8,11.21 30.8,11.53
  region net NetJ1_3: 30.55,11.53 ccw(c30.716,11.364) 30.481,11.364 30.481,11.21 30.8,11.21 30.8,11.53
  pour cut-out: 22.209,33.472 22.434,33.472 24.409,33.472 24.409,30.137 cw(c21.974,29.906) 23.859,28.347 cw(c22.988,29.081) 23.084,27.946 19.755,27.946 cw(c19.867,29.171) 18.921,28.385 cw(c19.946,29.322) 18.559,29.384 18.559,31.847 cw(c19.356,31.792) 18.834,32.397 cw(c19.481,31.731) 19.496,32.66 21.992,32.66 ccw(c21.781,33.054) 22.209,32.925
  region net NetJ1_1: 30.55,13.27 cw(c30.716,13.436) 30.481,13.436 30.481,13.59 30.8,13.59 30.8,13.27
  region net NetJ1_1: 31.05,13.27 ccw(c30.884,13.436) 31.119,13.436 31.119,13.59 30.8,13.59 30.8,13.27
  region net NetZ1_2: 37.102,5.002 36.102,5.002 36.102,8.502 31.692,8.502 31.692,9.002 36.602,9.002 36.602,5.502 39.102,5.502 39.102,4.002 37.102,4.002
  region net NetA2_4: 52.4,43 52.4,45.5 40.05,45.5 40.05,44.5 51.4,44.5 51.4,43
  region net NetA1_1: 31.219,2 40.596,2 40.596,2.5 31.219,2.5
  region net NetA1_1: 35.34,2 44.596,2 44.596,2.5 35.34,2.5
  region net VDD_BUCK: 19.159,28.628 19.159,29.572 19.334,29.747 22.759,29.747 23.059,29.447 23.059,28.703 22.809,28.453 19.334,28.453
  region net NetL6_1: 20.409,30.722 20.409,31.847 20.509,31.947 22.409,31.947 22.809,32.347 22.859,32.872 23.034,32.872 23.059,32.597 23.059,31.013 22.699,30.653 20.478,30.653
  region net GND: 19.084,29.947 18.969,30.062 18.969,31.832 19.109,31.972 20.109,31.972 20.234,31.847 20.234,30.647 20.409,30.472 22.834,30.472 23.234,30.872 23.234,32.372 23.859,32.372 23.859,31.672 23.984,31.547 23.984,30.472 23.459,29.947
  pour cut-out: 17.388,38.354 17.388,35.756 19.314,35.756 19.314,38.355
  region net RF4: 32.218,5.2 32.219,4.002 31.719,3.502 31.219,4.002 32.019,5.002 32.018,5.2
  region net RF1: 32.418,5.2 32.418,5 32.719,4.002 33.219,3.502 33.719,4.002 32.618,5 32.618,5.2
  region net RF2: 32.419,5.802 32.418,6 32.816,7.325 33.719,7.325 33.719,7.002 32.619,5.999 32.619,5.802 32.42,5.802 32.418,5.8
  region net RF3: 32.219,5.802 32.219,7.502 31.219,7.502 31.219,7.002 32.018,6 32.018,5.8
  region net RFC: 32.218,5.6 30.219,5.6 30.219,5.4 32.218,5.4
  pour cut-out: 37.07,0.25 30.757,0.25 30.757,9.202 37.07,9.202
  region net GND: 32.431,5.637 32.431,5.362 33.006,5.362 33.006,5.812 32.831,5.812 32.831,5.637
Mid Layer 1:
  rectangle net 1V8_SW: 12.503,18.116 13.745,18.879
  rectangle net 1V8_SW: 12.503,16.92 13,18.879
  region net VDD_nRF91: 27.686,10.415 25.63,10.415 25.63,9.335 27.686,9.335
  region net VBAT_nRF70: 20.102,34.125 19.302,34.125 19.302,32.425 20.102,32.425
  region net VSYS_SW: 7.487,38.743 7.487,36.618 8.637,36.618 8.637,38.743
  region net 1V8_SW: 4.1,12.43 4.1,12.042 5.8,12.042 5.8,12.43
  pour cut-out: 28.192,16.215 29.066,15.341 cw(c28.26,14.535) 29.4,14.535 29.4,13.56 ccw(c30.8,13.56) 32.2,13.56 32.2,14.535 ccw(c28.26,14.535) 31.046,17.321 30.173,18.195 ccw(c27.386,15.409) 27.45,19.349 ccw(c27.45,17.948) 27.45,16.547 cw(c27.386,15.409)
  pour cut-out: 25.242,18.1 25.661,18.1 ccw(c25.661,18.356) 25.842,18.175 25.842,17.725 ccw(c25.661,17.544) 25.661,17.8 25.242,17.8
  pour cut-out: 24.733,21.493 cw(c25.446,23.115) 24.309,21.756 23.212,22.627 cw(c25.09,22.226) 23.793,23.642 cw(c25.367,22.068) 25.367,24.294 32.036,24.294 ccw(c32.036,25.169) 32.654,24.549 32.656,24.552 ccw(c32.075,25.13) 32.895,25.131 32.895,31.648 ccw(c31.756,31.648) 32.561,32.454 31.049,33.966 cw(c33.836,36.752) 29.895,36.752 29.895,37.78 cw(c31.296,37.78) 32.696,37.78 32.696,36.752 ccw(c33.835,36.752) 33.03,35.946 34.542,34.434 cw(c31.756,31.648) 35.696,31.648 35.696,25.131 cw(c32.075,25.13) 34.635,22.57 cw(c32.036,25.169) 32.036,21.493
  pour cut-out: 24.367,21.175 24.367,21.594 ccw(c24.111,21.594) 24.292,21.775 24.742,21.775 ccw(c24.923,21.594) 24.667,21.594 24.667,21.175
  pour cut-out: 24.206,22.174 ccw(c24.519,22.087) 24.832,22 cw(c25.436,22) 25.008,22.425 25.009,22.426 cw(c25.367,22.068) 25.367,22.574 32.036,22.574 ccw(c32.036,25.169) 33.871,23.334 ccw(c32.075,25.131) 34.615,25.131 34.615,31.648 ccw(c31.756,31.648) 33.777,33.67 32.265,35.182 cw(c33.836,36.752) 31.615,36.752 31.615,37.78 ccw(c31.296,37.78) 30.976,37.78 30.976,36.752 ccw(c33.836,36.752) 31.814,34.73 33.326,33.218 cw(c31.756,31.648) 33.976,31.648 33.976,25.131 cw(c32.075,25.131) 33.42,23.787 33.418,23.785 cw(c32.036,25.169) 32.036,23.213 25.367,23.213 ccw(c25.367,22.068) 24.557,22.878 ccw(c25.436,22)
  pour cut-out: 17.582,47.278 cw(c17.582,47.623) 17.582,47.969 18.608,47.969 cw(c18.608,47.623) 18.953,47.623 cw(c18.608,47.623) 18.608,47.278
  pour cut-out: 19.604,43.95 19.604,44.376 cw(c21.024,44.376) 20.02,45.38 20.031,45.391 cw(c20.8,44.622) 20.8,45.709 ccw(c20.8,45.959) 20.975,45.782 21.01,45.816 ccw(c20.421,46.406) 21.254,46.406 21.254,47.201 21.183,47.278 20.928,47.278 cw(c20.928,47.623) 20.928,47.969 21.183,47.969 cw(c21.183,47.211) 21.719,47.747 cw(c21.173,47.201) 21.945,47.201 21.945,46.406 cw(c20.421,46.406) 21.499,45.327 21.465,45.293 cw(c20.8,45.959) 20.8,45.018 ccw(c20.8,44.622) 20.52,44.902 20.509,44.891 ccw(c21.024,44.376) 20.296,44.376 20.296,43.95 cw(c19.95,43.95)
  pour cut-out: 20.475,42.705 cw(c20.475,43.05) 20.475,43.395 23.324,43.395 cw(c23.324,41.824) 24.895,41.824 24.895,39.35 cw(c24.55,39.35) 24.205,39.35 24.205,41.824 ccw(c23.324,41.824) 23.324,42.705
  pour cut-out: 19.105,41.682 ccw(c19.45,41.682) 19.795,41.682 19.795,43.15 ccw(c19.45,43.15) 19.105,43.15
  pour cut-out: 20.145,40.905 cw(c20.145,41.25) 20.145,41.595 22.85,41.595 cw(c22.85,40.35) 24.095,40.35 24.095,39.35 cw(c23.75,39.35) 23.405,39.35 23.405,40.35 ccw(c22.85,40.35) 22.85,40.905
  pour cut-out: 16.008,32.048 ccw(c17.502,32.048) 17.502,30.555 18.075,30.555 ccw(c18.075,30.9) 18.42,30.9 ccw(c18.075,30.9) 18.075,31.245 17.502,31.245 cw(c17.502,32.048) 16.699,32.048 16.699,40.077 cw(c17.526,40.077) 17.526,40.905 18.757,40.905 ccw(c18.757,41.25) 19.102,41.25 ccw(c18.757,41.25) 18.757,41.595 17.526,41.595 ccw(c17.526,40.077) 16.008,40.077
  pour cut-out: 22.209,33.472 22.434,33.472 22.434,32.884 cw(c21.922,32.884) 22.284,32.522 cw(c21.982,32.824) 21.982,32.397 19.637,32.397 ccw(c19.637,31.545) 19.034,32.147 ccw(c19.515,31.665) 18.834,31.664 18.834,29.055 ccw(c19.516,29.055) 19.034,28.572 ccw(c19.697,29.235) 19.698,28.297 22.839,28.297 ccw(c22.839,29.492) 23.684,28.647 ccw(c21.709,30.126) 24.134,29.672 24.134,33.472 24.409,33.472 24.409,30.137 cw(c21.973,29.906) 23.859,28.347 cw(c22.987,29.082) 23.084,27.946 19.755,27.946 cw(c19.868,29.172) 18.921,28.385 cw(c19.946,29.322) 18.559,29.384 18.559,31.847 cw(c19.356,31.792) 18.834,32.397 cw(c19.481,31.731) 19.496,32.66 21.992,32.66 ccw(c21.781,33.054) 22.209,32.925
  region net VDD_BUCK: 23.513,28.865 23.513,29.29 ccw(c23.338,29.29) 23.338,29.465 22.888,29.465 ccw(c22.888,29.29) 22.713,29.29 22.713,28.865 ccw(c22.888,28.865) 22.888,28.69 23.338,28.69 ccw(c23.338,28.865)
  pour cut-out: 29.229,11.285 ccw(c30.219,10.295) 31.209,9.305 31.554,9.65 ccw(c29.994,11.21) 32.2,11.21 ccw(c30.8,11.21) 29.426,11.483
  pour cut-out: 29.644,5.387 29.644,5.521 ccw(c28.193,5.521) 29.219,6.547 cw(c30.186,7.514) 28.819,7.514 28.819,7.647 30.219,7.647 30.219,5.387
  pour cut-out: 30.795,5.387 30.795,5.521 cw(c32.246,5.521) 31.22,6.547 ccw(c30.253,7.514) 31.62,7.514 31.62,7.647 30.219,7.647 30.219,5.387
  pour cut-out: 31.619,10.325 31.619,7.45 cw(c30.219,7.45) 28.819,7.45 28.819,10.325
  pour cut-out: 31.054,33.966 32.566,32.454 cw(c31.76,31.648) 32.9,31.648 ccw(c34.3,31.648) 35.7,31.648 ccw(c31.76,31.648) 34.546,34.434 33.034,35.946 cw(c33.84,36.752) 32.7,36.752 32.7,39.256 ccw(c31.3,39.256) 29.9,39.256 29.9,36.752 ccw(c33.84,36.752)
  pour cut-out: 37.15,46.4 33.71,46.4 ccw(c33.71,45) 32.715,45.985 ccw(c33.7,44.99) 32.3,44.99 32.3,43.91 ccw(c33.7,43.91) 33.7,42.51 ccw(c33.7,43.91) 35.066,43.6 37.15,43.6 ccw(c37.15,45)
  pour cut-out: 32.3,41.55 32.3,44.99 cw(c33.7,44.99) 32.715,45.985 cw(c33.71,45) 33.71,46.4 34.79,46.4 cw(c34.79,45) 36.19,45 cw(c34.79,45) 35.1,43.634 35.1,41.55 cw(c33.7,41.55)
  pour cut-out: 19.358,26.178 18.345,26.178 18.345,24.978 19.358,24.978
  pour cut-out: 23.69,27.573 22.677,27.573 22.677,26.373 23.69,26.373
  pour cut-out: 25.842,17.725 26.767,16.55 28.789,16.55 27.294,19.35 26.767,19.35 25.842,18.175
  pour cut-out: 19.043,6.884 19.043,7.897 17.844,7.897 17.844,6.884
  pour cut-out: 6.035,45.931 7.048,45.931 7.048,47.127 6.035,47.127
  pour cut-out: 5.546,15.179 6.744,15.179 6.744,17.364 5.546,17.364
  pour cut-out: 23.405,39.35 23.405,38.231 24.895,38.231 24.895,39.35
  pour cut-out: 18.25,40.905 20.681,40.905 20.681,45.025 18.25,45.025
  pour cut-out: 37.07,0.25 30.757,0.25 30.757,8.386 37.07,8.386
  pour cut-out: 32.019,5.2 32.019,5 31.359,4.339 31.359,3.304 32.069,3.304 32.069,3.914 32.219,4.065 32.219,5.2
  pour cut-out: 32.619,5.2 32.619,5 33.28,4.339 33.28,3.304 32.57,3.304 32.57,3.914 32.419,4.065 32.419,5.2
  pour cut-out: 33.499,4.123 32.619,5.2 32.019,5.2 31.139,4.124
  pour cut-out: 33.499,6.876 32.619,5.8 32.019,5.8 31.139,6.875
  pour cut-out: 32.019,5.8 32.019,6 31.359,6.66 31.359,7.695 32.069,7.695 32.069,7.085 32.219,6.935 32.219,5.8
  pour cut-out: 32.619,5.8 32.619,6 33.28,6.66 33.28,7.695 32.57,7.695 32.57,7.085 32.419,6.935 32.419,5.8
  pour cut-out: 38.45,3.643 31.59,3.643 31.59,0.843 38.45,0.843
  pour cut-out: 38.45,10.15 31.59,10.15 31.59,7.35 38.45,7.35
  pour cut-out: 35.403,3.603 35.403,10.15 38.203,10.15 38.203,3.603
  pour cut-out: 37.565,5.012 36.566,5.012 36.566,8.512 31.81,8.512 31.81,8.987 37.041,8.987 37.041,5.487 39.541,5.487 39.541,4.012 37.565,4.012
  pour cut-out: 30.575,14.823 29.4,13.898 29.4,11.198 32.2,11.198 32.2,13.898 31.025,14.823
  pour cut-out: 35.34,2 44.596,2 44.596,2.487 35.34,2.487
Mid Layer 2:
  rectangle net VDD_nRF91: 25.629,9.335 26.538,10.415
  rectangle net VBAT_nRF70: 10.15,31.625 11.7,32.125
  region net VBAT_nRF70: 19.3,34.125 19.3,33.25 20.1,33.25 20.1,34.125
  region net 1V8_SW: 4.1,12.43 4.1,12.042 5.8,12.042 5.8,12.43
  rectangle net VDD_nRF91: 12.85,13.475 14.95,14.556
  pour cut-out: 24.367,21.175 24.367,21.594 ccw(c24.111,21.594) 24.292,21.775 24.742,21.775 ccw(c24.923,21.594) 24.667,21.594 24.667,21.175
  pour cut-out: 25.242,18.1 25.661,18.1 ccw(c25.661,18.356) 25.842,18.175 25.842,17.725 ccw(c25.661,17.544) 25.661,17.8 25.242,17.8
  pour cut-out: 28.192,16.215 29.066,15.341 cw(c28.26,14.535) 29.4,14.535 29.4,13.56 ccw(c30.8,13.56) 32.2,13.56 32.2,14.535 ccw(c28.26,14.535) 31.046,17.321 30.173,18.195 ccw(c27.386,15.409) 27.45,19.349 ccw(c27.45,17.948) 27.45,16.547 cw(c27.386,15.409)
  pour cut-out: 24.733,21.493 cw(c25.446,23.115) 24.309,21.756 23.212,22.627 cw(c25.09,22.226) 23.793,23.642 cw(c25.367,22.068) 25.367,24.294 32.036,24.294 ccw(c32.036,25.169) 32.654,24.549 32.656,24.552 ccw(c32.075,25.13) 32.895,25.131 32.895,31.648 ccw(c31.756,31.648) 32.561,32.454 31.049,33.966 cw(c33.836,36.752) 29.895,36.752 29.895,37.78 cw(c31.296,37.78) 32.696,37.78 32.696,36.752 ccw(c33.835,36.752) 33.03,35.946 34.542,34.434 cw(c31.756,31.648) 35.696,31.648 35.696,25.131 cw(c32.075,25.13) 34.635,22.57 cw(c32.036,25.169) 32.036,21.493
  pour cut-out: 37.15,46.4 33.71,46.4 ccw(c33.71,45) 32.715,45.985 ccw(c33.7,44.99) 32.3,44.99 32.3,43.91 ccw(c33.7,43.91) 33.7,42.51 ccw(c33.7,43.91) 35.066,43.6 37.15,43.6 ccw(c37.15,45)
  pour cut-out: 32.3,41.55 32.3,44.99 cw(c33.7,44.99) 32.715,45.985 cw(c33.71,45) 33.71,46.4 34.79,46.4 cw(c34.79,45) 36.19,45 cw(c34.79,45) 35.1,43.634 35.1,41.55 cw(c33.7,41.55)
  pour cut-out: 31.054,33.966 32.566,32.454 cw(c31.76,31.648) 32.9,31.648 ccw(c34.3,31.648) 35.7,31.648 ccw(c31.76,31.648) 34.546,34.434 33.034,35.946 cw(c33.84,36.752) 32.7,36.752 32.7,39.256 ccw(c31.3,39.256) 29.9,39.256 29.9,36.752 ccw(c33.84,36.752)
  pour cut-out: 29.644,5.387 29.644,5.521 ccw(c28.193,5.521) 29.219,6.547 cw(c30.186,7.514) 28.819,7.514 28.819,7.647 30.219,7.647 30.219,5.387
  pour cut-out: 30.795,5.387 30.795,5.521 cw(c32.246,5.521) 31.22,6.547 ccw(c30.253,7.514) 31.62,7.514 31.62,7.647 30.219,7.647 30.219,5.387
  pour cut-out: 31.619,10.325 31.619,7.45 cw(c30.219,7.45) 28.819,7.45 28.819,10.325
  pour cut-out: 29.229,11.285 ccw(c30.219,10.295) 31.209,9.305 31.554,9.65 ccw(c29.994,11.21) 32.2,11.21 ccw(c30.8,11.21) 29.426,11.483
  region net VDD_BUCK: 23.513,29.29 ccw(c23.338,29.29) 23.338,29.465 ccw(c23.338,29.29) 23.163,29.29 23.163,28.865 ccw(c23.338,28.865) 23.338,28.69 ccw(c23.338,28.865) 23.513,28.865
  pour cut-out: 19.358,26.178 18.345,26.178 18.345,24.978 19.358,24.978
  pour cut-out: 23.69,27.573 22.677,27.573 22.677,26.373 23.69,26.373
  pour cut-out: 25.842,17.725 26.767,16.55 28.789,16.55 27.294,19.35 26.767,19.35 25.842,18.175
  pour cut-out: 19.043,6.884 19.043,7.897 17.844,7.897 17.844,6.884
  pour cut-out: 6.035,45.931 7.048,45.931 7.048,47.127 6.035,47.127
  pour cut-out: 5.546,15.179 6.744,15.179 6.744,17.364 5.546,17.364
  pour cut-out: 37.98,10.15 31.12,10.15 31.12,7.35 37.98,7.35
  pour cut-out: 35.403,3.603 35.403,10.15 38.203,10.15 38.203,3.603
  pour cut-out: 37.565,5.012 36.566,5.012 36.566,8.512 31.81,8.512 31.81,8.987 37.041,8.987 37.041,5.487 39.541,5.487 39.541,4.012 37.565,4.012
  pour cut-out: 37.07,0.25 30.757,0.25 30.757,8.386 37.07,8.386
  pour cut-out: 38.45,3.643 31.59,3.643 31.59,0.843 38.45,0.843
  pour cut-out: 32.619,5.2 32.619,5 33.28,4.339 33.28,3.304 32.57,3.304 32.57,3.914 32.419,4.065 32.419,5.2
  pour cut-out: 33.499,4.123 32.619,5.2 32.019,5.2 31.139,4.124
  pour cut-out: 32.019,5.2 32.019,5 31.359,4.339 31.359,3.304 32.069,3.304 32.069,3.914 32.219,4.065 32.219,5.2
  pour cut-out: 33.499,6.876 32.619,5.8 32.019,5.8 31.139,6.875
  pour cut-out: 32.619,5.8 32.619,6 33.28,6.66 33.28,7.695 32.57,7.695 32.57,7.085 32.419,6.935 32.419,5.8
  pour cut-out: 32.019,5.8 32.019,6 31.359,6.66 31.359,7.695 32.069,7.695 32.069,7.085 32.219,6.935 32.219,5.8
  pour cut-out: 30.575,14.823 29.4,13.898 29.4,11.198 32.2,11.198 32.2,13.898 31.025,14.823
  pour cut-out: 35.81,2 45.066,2 45.066,2.487 35.81,2.487
Mid Layer 3:
  rectangle net 3V3: 22.426,39.097 23.042,39.842
  rectangle net VBAT_nRF70: 9.775,31.6 11.425,32.275
  region net 1V8_SW: 12.5,19.135 12.5,17.46 13,17.46 13,19.135
  region net VDD_nRF53: 11.7,19.16 11.7,17.485 12.2,17.485 12.2,19.16
  region net 3V3: 9.275,14.575 9.275,13.025 9.775,13.025 9.775,14.575
  region net VSYS_SW: 7.562,38.743 7.562,36.55 8.562,36.55 8.562,38.743
  rectangle net VSYS_SW: 12.8,35.025 14.512,36.025
  region net VBAT_nRF70: 9.55,31.7 9.05,31.7 9.05,30.175 9.55,30.175
  region net VBUS: 5.075,38.8 5.075,38.3 6.925,38.3 6.925,38.8
  rectangle net VBUS_CONN: 7.35,27.95 8.2,31.225
  region net VBUS: 7.332,42.225 7.332,43.1 5.7,43.1 5.7,42.225
  region net VOUT_BUCK3: 6.45,6.05 6.45,6.55 4.75,6.55 4.75,6.05
  region net VBAT_nRF70: 6.45,6.85 6.45,7.35 4.75,7.35 4.75,6.85
  region net VDD_nRF53: 6.275,8.45 6.275,8.95 4.75,8.95 4.75,8.45
  region net 1V8_SW: 6.275,7.65 6.275,8.15 4.75,8.15 4.75,7.65
  region net GND: 25.167,18.1 25.661,18.1 ccw(c25.661,18.356) 25.842,18.175 25.842,17.725 ccw(c25.661,17.544) 25.661,17.8 25.167,17.8
  region net VDD_SENS: 21.1,43.075 21.625,43.075 cw(c21.625,42.825) 21.875,42.825 cw(c21.625,42.825) 21.625,42.575 21.1,42.575
  region net GND: 31.054,33.966 32.566,32.454 cw(c31.76,31.648) 32.9,31.648 ccw(c34.3,31.648) 35.7,31.648 ccw(c31.76,31.648) 34.546,34.434 33.034,35.946 cw(c33.84,36.752) 32.7,36.752 32.7,39.256 ccw(c31.3,39.256) 29.9,39.256 29.9,36.752 ccw(c33.84,36.752)
  region net GND: 30.795,5.387 30.795,5.521 cw(c32.246,5.521) 31.22,6.547 ccw(c30.253,7.514) 31.62,7.514 31.62,7.647 30.219,7.647 30.219,5.387
  region net GND: 29.229,11.285 ccw(c30.219,10.295) 31.209,9.305 31.554,9.65 ccw(c29.994,11.21) 32.2,11.21 ccw(c30.8,11.21) 29.426,11.483
  region net GND: 31.619,10.325 31.619,7.45 cw(c30.219,7.45) 28.819,7.45 28.819,10.325
  region net GND: 29.644,5.387 29.644,5.521 ccw(c28.193,5.521) 29.219,6.547 cw(c30.186,7.514) 28.819,7.514 28.819,7.647 30.219,7.647 30.219,5.387
  region net VOUT_BUCK3: 8.375,33.133 8.602,33.36 9.127,33.36 cw(c9.127,33.16) 9.327,33.16 9.327,32.685 8.777,32.135 8.375,32.135
  region net VBAT_nRF70: 9.05,31.7 9.05,31.95 9.375,32.275 9.9,32.275 cw(c9.9,32.075) 10.1,32.075 10.1,31.6 9.55,31.05 9.05,31.05
  region net 3V3: 22.535,39.842 22.285,39.842 21.932,39.489 21.932,39.185 22.02,39.097 22.135,39.097 22.535,39.097
  region net GND: 32.619,5.8 32.619,6 33.28,6.66 33.28,7.695 32.57,7.695 32.57,7.085 32.419,6.935 32.419,5.8
  region net GND: 32.019,5.8 32.019,6 31.359,6.66 31.359,7.695 32.069,7.695 32.069,7.085 32.219,6.935 32.219,5.8
  region net GND: 33.499,6.876 32.619,5.8 32.019,5.8 31.139,6.875
  region net GND: 33.499,4.123 32.619,5.2 32.019,5.2 31.139,4.124
  region net GND: 32.619,5.2 32.619,5 33.28,4.339 33.28,3.304 32.57,3.304 32.57,3.914 32.419,4.065 32.419,5.2
  region net GND: 32.019,5.2 32.019,5 31.359,4.339 31.359,3.304 32.069,3.304 32.069,3.914 32.219,4.065 32.219,5.2
  region net VBUS_CONN: 8.2,31.133 8.2,32.3 7.85,32.65 6.275,32.65 6.275,32.3 7.35,31.225
  region net VBUS: 6.925,38.798 5.573,40.15 5.078,40.15 5.078,38.728 5.1,38.75 6.925,38.75
  region net NetC9_2: 15,42.85 15,40.575 13.325,38.9 7,38.9 5.7,40.2 5.7,41.4 7.975,41.4 7.975,40.525 8.7,39.8 12.85,39.8 13.993,40.943 13.993,42.85
  pour cut-out: 36.75,48.311 42.25,48.311 42.25,53.229 36.75,53.229
Mid Layer 4:
  rectangle net 3V3: 22.081,39.096 24.351,39.848
  region net 3V3_IND: 18.487,38.333 18.487,40.905 17.987,40.905 17.987,38.333
  region net GND: 16.3,38.2 16.3,40.2 14.668,40.2 14.668,38.2
  rectangle net GND: 13.575,43.132 14.925,44.434
  region net VDD_SENS: 21.038,43 21.038,42.225 21.825,42.225 21.825,43
  region net VDD_nRF53: 12.2,17.525 12.2,21.075 11.7,21.075 11.7,17.525
  region net 1V8_SW: 13,16.92 13,19.585 12.5,19.585 12.5,16.92
  region net 3V3: 9.275,14.7 9.275,11.4 9.775,11.4 9.775,14.7
  region net VBAT_nRF70: 8.445,32.3 8.445,31.475 11.425,31.475 11.425,32.3
  region net VOUT_BUCK3: 8.45,33.375 8.45,32.55 10.445,32.55 10.445,33.375
  region net NetC9_2: 5.7,41.68 5.7,39.805 8,39.805 8,41.68
  rectangle net VSYS_SW: 12.85,31.263 14.537,32.038
  rectangle net VSYS_SW: 12.85,35.113 14.537,35.888
  region net VBUS: 6.925,38.75 5.075,38.75 5.075,37.95 6.925,37.95
  rectangle net VBUS_CONN: 6.3,32.275 7.925,33.025
  region net VBUS: 7.332,41.825 7.332,43.1 5.7,43.1 5.7,41.825
  region net NetC9_2: 15.625,40.85 15.625,42.85 13.993,42.85 13.993,40.85
  region net 1V8_SW: 12.5,21.075 12.5,19.425 13,19.425 13,21.075
  region net VSYS_SW: 10.65,16.725 10.65,15.05 11.15,15.05 11.15,16.725
  rectangle net VOUT_BUCK3: 3.15,6.05 6.45,6.55
  region net VSYS_SW: 10.4,16 10.4,17.65 9.9,17.65 9.9,16
  rectangle net VDD_nRF53: 3.15,8.45 6.45,8.95
  region net VDD_nRF91: 13.35,13.35 11.35,13.35 11.35,12.85 13.35,12.85
  rectangle net 1V8_SW: 3.15,7.65 6.45,8.15
  rectangle net VBAT_nRF70: 3.15,6.85 6.45,7.35
  pour cut-out: 23.954,26.051 23.954,26.097 cw(c24.453,26.097) 24.1,26.45 ccw(c23.848,26.702) 24.204,26.702 24.204,26.902 24.895,26.902 24.895,26.73 cw(c24.57,26.73) 24.8,26.5 ccw(c25.175,26.125) 24.645,26.125 24.645,26.051
  pour cut-out: 22.231,24.735 cw(c22.231,25.08) 22.231,25.425 23.704,25.425 ccw(c23.704,25.676) 23.954,25.676 23.954,26.051 cw(c24.299,26.051) 24.645,26.051 24.645,25.676 cw(c23.704,25.676) 23.704,24.735
  pour cut-out: 23.65,30.555 cw(c23.65,30) 24.204,30 ccw(c24.55,30) 24.204,29.999 24.204,26.902 ccw(c24.55,26.902) 24.895,26.902 24.895,30 ccw(c24.55,30) 24.895,30.002 cw(c23.65,30) 24.895,30 24.895,30.002 ccw(c23.65,30) 23.65,31.245 18.075,31.245 ccw(c18.075,30.9) 18.075,30.555
  region net VBUS_CONN: 8.975,29.175 7.325,29.175 7.325,27.975 8.075,27.975 8.975,28.875
  pour cut-out: 36.75,48.311 42.25,48.311 42.25,53.229 36.75,53.229
  region net VSYS_SW: 10.65,15.05 9.9,15.8 9.9,17.055 10.32,17.055 10.7,16.675 10.7,15.05
  region net VDD_nRF91: 12.005,13.35 12.246,13.35 13.447,14.55 14.95,14.55 14.95,14.15 13.65,12.85 12.005,12.85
